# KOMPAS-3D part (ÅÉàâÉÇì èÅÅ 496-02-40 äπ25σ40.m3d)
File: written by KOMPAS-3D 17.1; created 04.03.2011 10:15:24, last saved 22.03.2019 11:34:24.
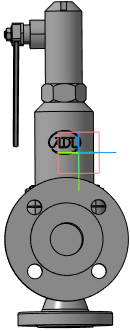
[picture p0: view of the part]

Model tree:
1. Плоскость XY
2. Плоскость ZX
3. Плоскость ZY
4. Ось X
5. Ось Y
6. Ось Z
7. Начало координат
8. Операция без истории:2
